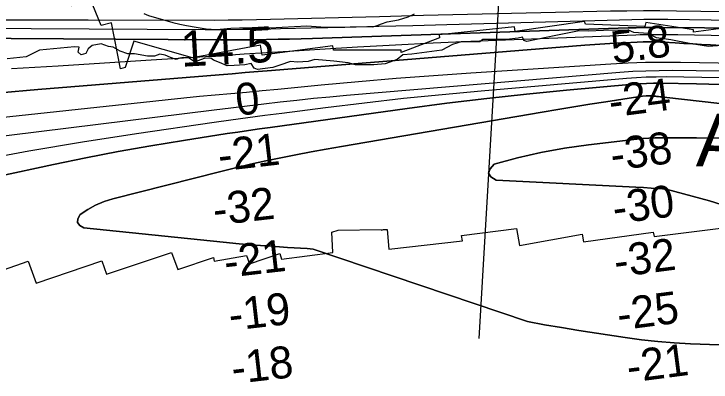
# Model space of a CAD drawing. Extents: x 3219052 to 3256913, y 800770 to 826146.
# Drawn here: x 3229358 to 3230665, y 817096 to 817787 of the extents above; entities that cross this region are included whole.
import ezdxf

# ---------------------------------------------------------------- set-up
doc = ezdxf.new("R2010")
doc.units = 0
for name, color, linetype in [('V-RIVR-EDGE', 7, 'Continuous'), ('V-RIVR-RANG', 7, 'Continuous'), ('V-RRAP-RVMT', 7, 'Continuous'), ('V-RRAP-RVMT-IDEN', 7, 'Continuous'), ('V-SITE-VEGE', 7, 'Continuous'), ('V-TOPO-DPTH', 7, 'Continuous'), ('V-TOPO-MINR', 7, 'Continuous'), ('V-TOPO-WATR', 7, 'Continuous')]:
    doc.layers.add(name, color=color, linetype=linetype)

msp = doc.modelspace()

# ---------------------------------------------------------------- linework, layer by layer
at = {"layer": 'V-RIVR-EDGE'}
for points in [[(3230693.3, 817727.8), (3230659.8, 817725.7), (3230624.2, 817731), (3230589.4, 817738.1), (3230562.5, 817741.6), (3230546.4, 817749.9), (3230519.9, 817752.1), (3230509.9, 817756.5), (3230463, 817755.8), (3230435.1, 817754.1), (3230417.3, 817755), (3230373.4, 817746), (3230319, 817735.2), (3230313.4, 817736.6), (3230310.8, 817743.1), (3230303, 817741.4), (3230281.2, 817738.8), (3230236.5, 817738.9), (3230231.2, 817734.6), (3230225.1, 817734.2), (3230196, 817734.2), (3230179.9, 817729.1), (3230159.9, 817718.7), (3230103.8, 817711.4), (3230086.9, 817709.7), (3230076, 817701.5), (3230053.8, 817692.9), (3230032.5, 817691.2), (3229998.1, 817691.3), (3229984.2, 817695.2), (3229957.3, 817698.3), (3229921.7, 817701), (3229909.5, 817697.6), (3229889, 817696.3), (3229876, 817697.2), (3229856.4, 817690.8), (3229842.9, 817686), (3229814.2, 817682.2), (3229808.2, 817685.2), (3229802.1, 817693.9), (3229790.4, 817691.3), (3229770.4, 817689.7), (3229757.3, 817689.3), (3229743, 817695.4), (3229731.7, 817699.8), (3229726.5, 817703.7), (3229714.3, 817702.8), (3229702.1, 817698.5), (3229695.6, 817697.7), (3229685.2, 817704.2), (3229675.6, 817704.7), (3229668.7, 817703.8), (3229661.7, 817701.2), (3229651.3, 817705.2), (3229641.3, 817709.5), (3229631.3, 817711.3), (3229621.3, 817707.4), (3229608.3, 817707.4), (3229583.5, 817711.9), (3229571.3, 817711.9), (3229556.6, 817717.1), (3229543.5, 817724.6), (3229534.8, 817725.9), (3229521.4, 817730.7), (3229504, 817727.7), (3229497, 817721.2), (3229492.7, 817712.5)], [(3229492.7, 817712.5), (3229483.5, 817709.9), (3229478.3, 817715.2), (3229480.1, 817724.3), (3229471.4, 817725.2), (3229405.7, 817718.8), (3229380.5, 817706.3), (3229344.8, 817702.4)]]:
    msp.add_lwpolyline(points, dxfattribs=at)
at = {"layer": 'V-RIVR-RANG'}
msp.add_line((3230269.4, 817868.1), (3230229, 817177.3), dxfattribs=at)
at = {"layer": 'V-RRAP-RVMT'}
for points in [[(3230083.5, 817714.2), (3230083.5, 817718.7), (3229956.5, 817718.7), (3229955.5, 817727.1), (3229822.9, 817709.5), (3229819.6, 817728.4), (3229692.5, 817704.4), (3229582.2, 817735.4), (3229566.3, 817686), (3229557.5, 817683.8), (3229540.8, 817769.9), (3229521.1, 817764.9), (3229499.8, 817817.6), (3229465.8, 817802.2), (3229392, 817823.7), (3229393, 817834.5), (3229255, 817843.4)], [(3230838.7, 817753.6), (3230834.2, 817753.3), (3230832.5, 817762.2), (3230690.4, 817741.2), (3230688.1, 817759.9), (3230631.6, 817752.8), (3230631.4, 817756.7), (3230542.5, 817770.8), (3230540.4, 817762.9), (3230428.9, 817767.3), (3230427.6, 817772.6), (3230297.1, 817753.7), (3230295.9, 817762.3), (3230155.1, 817747.8), (3230155.7, 817741.9), (3230083.5, 817714.2)], [(3229255.6, 817277.6), (3229384, 817322.5), (3229399.5, 817281.5), (3229522.4, 817323.2), (3229531.4, 817298), (3229653.3, 817339.2), (3229665, 817307.2), (3229731.8, 817329.4), (3229732.7, 817322.7), (3229793.7, 817333.3), (3229799.5, 817317.6), (3229856.2, 817336.9), (3229859.2, 817326.7), (3229955.8, 817339), (3229953.8, 817377), (3229965.3, 817381), (3230046.4, 817382), (3230046.8, 817381), (3230050.5, 817382.1), (3230057.3, 817382.1), (3230060.7, 817345.5), (3230198.3, 817361.1), (3230197, 817371), (3230300, 817384.1), (3230305.6, 817352.1), (3230423, 817373.4), (3230425.4, 817358.7), (3230556.3, 817377.4), (3230557.8, 817369), (3230812, 817401.2)]]:
    msp.add_lwpolyline(points, dxfattribs=at)
at = {"layer": 'V-SITE-VEGE'}
for p, q in [((3229601.3, 817787.3), (3229609.6, 817783.7)), ((3229609.6, 817783.7), (3229655.3, 817770.4)), ((3230078.7, 817775.4), (3230096.6, 817781.3)), ((3230096.6, 817781.3), (3230108.4, 817786.7)), ((3229655.3, 817770.4), (3229668.5, 817767.3)), ((3229668.5, 817767.3), (3229681.2, 817764.8)), ((3230038.7, 817764.8), (3230046.6, 817768.4)), ((3230046.6, 817768.4), (3230057.1, 817772.1)), ((3230057.1, 817772.1), (3230078.7, 817775.4)), ((3229681.2, 817764.8), (3229699.2, 817761.6)), ((3229699.2, 817761.6), (3229718.3, 817759)), ((3229718.3, 817759), (3229737.6, 817757.6)), ((3229737.6, 817757.6), (3229764.1, 817760.3)), ((3229764.1, 817760.3), (3229780.2, 817760.5)), ((3229780.2, 817760.5), (3229793.8, 817760.4)), ((3229793.8, 817760.4), (3229837.6, 817760.9)), ((3229837.6, 817760.9), (3229906.8, 817764.3)), ((3229906.8, 817764.3), (3229933.2, 817762.3)), ((3229933.2, 817762.3), (3229943.5, 817761.6)), ((3229943.5, 817761.6), (3229956.7, 817761.8)), ((3229956.7, 817761.8), (3230018.8, 817763.2)), ((3230018.8, 817763.2), (3230030.7, 817762.8)), ((3230030.7, 817762.8), (3230038.7, 817764.8))]:
    msp.add_line(p, q, dxfattribs=at)
at = {"layer": 'V-TOPO-DPTH'}
for points in [[(3229057.5, 817742.8), (3229744.6, 817738.1), (3229766.2, 817738), (3229787.8, 817738), (3229809.4, 817738.3), (3229831, 817738.6), (3229852.7, 817739.1), (3229874.3, 817739.6), (3229895.9, 817740.2), (3229917.5, 817740.9), (3230509, 817760.5), (3230524.1, 817760.9), (3230539.1, 817761.2), (3230554.2, 817761.2), (3230569.3, 817761.2), (3230652.5, 817760.4), (3230709.1, 817759.4)], [(3229331, 817638.8), (3229402.6, 817645), (3229742.5, 817672.6), (3229766.9, 817674.6), (3229791.4, 817676.6), (3229815.8, 817678.6), (3229840.2, 817680.5), (3230427.8, 817728), (3230446.5, 817729.4), (3230465.3, 817730.7), (3230484, 817731.8), (3230502.8, 817732.7), (3230537.2, 817734.3), (3230538.8, 817734.4), (3230540.3, 817734.4), (3230543.4, 817734.4), (3230552, 817734.4), (3230557.9, 817734.3), (3230563.8, 817734.1), (3230569.7, 817733.9), (3230575.6, 817733.6), (3230597, 817732.5), (3230613.6, 817731.5), (3230630.2, 817730.6), (3230646.8, 817729.6), (3230663.4, 817728.5), (3231005.5, 817707)], [(3231005.5, 817707), (3230663.4, 817728.5), (3230646.8, 817729.6), (3230630.2, 817730.6), (3230613.6, 817731.5), (3230597, 817732.5), (3230575.6, 817733.6), (3230569.7, 817733.9), (3230563.8, 817734.1), (3230557.9, 817734.3), (3230552, 817734.4), (3230543.4, 817734.4), (3230540.3, 817734.4), (3230538.8, 817734.4), (3230537.2, 817734.3), (3230502.8, 817732.7), (3230484, 817731.8), (3230465.3, 817730.7), (3230446.5, 817729.4), (3230427.8, 817728), (3229840.2, 817680.5), (3229815.8, 817678.6), (3229791.4, 817676.6), (3229766.9, 817674.6), (3229742.5, 817672.6), (3229402.6, 817645), (3229331, 817638.8)], [(3230725.5, 817678.7), (3230592, 817680.3), (3230567.3, 817680.2), (3230542.6, 817679.6), (3230518, 817678.4), (3230493.4, 817676.7), (3229981.1, 817633.5), (3229950.1, 817630.8), (3229919, 817627.8), (3229888, 817624.5), (3229857, 817621), (3229826, 817617.3), (3229795, 817613.6), (3229764, 817609.8), (3229733.1, 817606), (3229241.6, 817545.5)], [(3230725.5, 817678.7), (3230592, 817680.3), (3230567.3, 817680.2), (3230542.6, 817679.6), (3230518, 817678.4), (3230493.4, 817676.7), (3229981.1, 817633.5), (3229950.1, 817630.8), (3229919, 817627.8), (3229888, 817624.5), (3229857, 817621), (3229826, 817617.3), (3229795, 817613.6), (3229764, 817609.8), (3229733.1, 817606), (3229241.6, 817545.5)], [(3229327, 817481.4), (3229431.9, 817504.2), (3229492.5, 817516.8), (3229553.3, 817528.6), (3229614.2, 817539.3), (3229675.3, 817549.3), (3229757.6, 817562.1), (3229777.6, 817565.1), (3229797.6, 817568.1), (3229817.7, 817570.9), (3229837.7, 817573.8), (3230094.6, 817609.3), (3230169.2, 817619.1), (3230243.9, 817628.2), (3230318.7, 817636.1), (3230393.7, 817643.4), (3230518.3, 817654.6), (3230530.9, 817655.6), (3230543.6, 817656.3), (3230556.4, 817656.5), (3230569.1, 817656.6), (3230637, 817655.7), (3230683.6, 817654.5)], [(3229327, 817481.4), (3229431.9, 817504.2), (3229492.5, 817516.8), (3229553.3, 817528.6), (3229614.2, 817539.3), (3229675.3, 817549.3), (3229757.6, 817562.1), (3229777.6, 817565.1), (3229797.6, 817568.1), (3229817.7, 817570.9), (3229837.7, 817573.8), (3230094.6, 817609.3), (3230169.2, 817619.1), (3230243.9, 817628.2), (3230318.7, 817636.1), (3230393.7, 817643.4), (3230518.3, 817654.6), (3230530.9, 817655.6), (3230543.6, 817656.3), (3230556.4, 817656.5), (3230569.1, 817656.6), (3230637, 817655.7), (3230683.6, 817654.5)], [(3230819.4, 817603.1), (3230576.3, 817630.5), (3230572.9, 817630.9), (3230569.4, 817631.3), (3230566, 817631.7), (3230562.6, 817632), (3230561.2, 817632.2), (3230558.5, 817632.5), (3230555.7, 817632.7), (3230552.9, 817632.8), (3230550.2, 817632.9), (3230545.4, 817633), (3230543.9, 817632.9), (3230543.1, 817632.8), (3230536.1, 817632.2), (3230531.9, 817631.7), (3230527.6, 817631.2), (3230523.4, 817630.7), (3230519.2, 817630), (3230467.6, 817621.9), (3230437.6, 817617.1), (3230407.6, 817612.2), (3230377.6, 817607.2), (3230347.7, 817602.2), (3229971.7, 817538.1), (3229943.2, 817533.1), (3229914.7, 817528), (3229886.3, 817522.5), (3229858, 817516.9), (3229829.6, 817510.9), (3229801.4, 817504.7), (3229773.3, 817498), (3229745.2, 817491.1), (3229542.8, 817439.7), (3229526.5, 817434.5), (3229510.8, 817428), (3229496, 817419.6), (3229481.8, 817410), (3229477.7, 817402.1), (3229476.9, 817395.2), (3229481.2, 817389.7), (3229488.8, 817385.2), (3229749.9, 817358.4), (3229780, 817355.5), (3229810.1, 817352.9), (3229840.3, 817350.6), (3229870.4, 817348.5), (3229907.1, 817346.3), (3229918.9, 817345.1), (3230320.2, 817209.7), (3230352.2, 817203.5), (3230384.4, 817197.9), (3230416.6, 817192.7), (3230503.5, 817179.4), (3230534, 817175.3), (3230564.7, 817171.8), (3230595.4, 817169.4), (3230626.2, 817167.6), (3230679.7, 817165.4)], [(3230679.7, 817165.4), (3230626.2, 817167.6), (3230595.4, 817169.4), (3230564.7, 817171.8), (3230534, 817175.3), (3230503.5, 817179.4), (3230416.6, 817192.7), (3230384.4, 817197.9), (3230352.2, 817203.5), (3230320.2, 817209.7), (3229918.9, 817345.1), (3229907.1, 817346.3), (3229870.4, 817348.5), (3229840.3, 817350.6), (3229810.1, 817352.9), (3229780, 817355.5), (3229749.9, 817358.4), (3229488.8, 817385.2), (3229481.2, 817389.7), (3229476.9, 817395.2), (3229477.7, 817402.1), (3229481.8, 817410), (3229496, 817419.6), (3229510.8, 817428), (3229526.5, 817434.5), (3229542.8, 817439.7), (3229745.2, 817491.1), (3229773.3, 817498), (3229801.4, 817504.7), (3229829.6, 817510.9), (3229858, 817516.9), (3229886.3, 817522.5), (3229914.7, 817528), (3229943.2, 817533.1), (3229971.7, 817538.1), (3230347.7, 817602.2), (3230377.6, 817607.2), (3230407.6, 817612.2), (3230437.6, 817617.1), (3230467.6, 817621.9), (3230519.2, 817630), (3230523.4, 817630.7), (3230527.6, 817631.2), (3230531.9, 817631.7), (3230536.1, 817632.2), (3230543.1, 817632.8), (3230543.9, 817632.9), (3230545.4, 817633), (3230550.2, 817632.9), (3230552.9, 817632.8), (3230555.7, 817632.7), (3230558.5, 817632.5), (3230561.2, 817632.2), (3230562.6, 817632), (3230566, 817631.7), (3230569.4, 817631.3), (3230572.9, 817630.9), (3230576.3, 817630.5), (3230819.4, 817603.1)], [(3230682, 817553.7), (3230637.4, 817553.9), (3230570.7, 817554.1), (3230559.4, 817554), (3230548.1, 817553.5), (3230536.8, 817552.7), (3230525.5, 817551.6), (3230434.6, 817541), (3230390, 817534.6), (3230345.6, 817526.7), (3230301.8, 817516.5), (3230258.2, 817504.8), (3230250.2, 817496.1), (3230247.3, 817488.1), (3230252, 817481), (3230261.9, 817474.5), (3230523.5, 817461.6), (3230537.8, 817460.8), (3230552, 817460), (3230566.3, 817458.9), (3230580.6, 817457.8), (3230661.5, 817435.9), (3230790.5, 817395.1)], [(3230790.5, 817395.1), (3230661.5, 817435.9), (3230580.6, 817457.8), (3230566.3, 817458.9), (3230552, 817460), (3230537.8, 817460.8), (3230523.5, 817461.6), (3230261.9, 817474.5), (3230252, 817481), (3230247.3, 817488.1), (3230250.2, 817496.1), (3230258.2, 817504.8), (3230301.8, 817516.5), (3230345.6, 817526.7), (3230390, 817534.6), (3230434.6, 817541), (3230525.5, 817551.6), (3230536.8, 817552.7), (3230548.1, 817553.5), (3230559.4, 817554), (3230570.7, 817554.1), (3230637.4, 817553.9), (3230682, 817553.7)]]:
    msp.add_lwpolyline(points, dxfattribs=at)
at = {"layer": 'V-TOPO-MINR'}
for points in [[(3230826.8, 817788.7), (3230599.5, 817792.1), (3230568.6, 817792.4), (3230537.8, 817792.5), (3230506.9, 817792.2), (3230476, 817791.7), (3230372.9, 817789.4), (3230290.4, 817787.5), (3230207.9, 817785.6), (3230125.5, 817783.5), (3230043, 817781.4), (3229838.5, 817776), (3229812.1, 817775.4), (3229785.7, 817775), (3229759.3, 817774.8), (3229732.9, 817774.7), (3229496.5, 817775.2), (3229407.6, 817775.2), (3229318.6, 817774.9)], [(3230705.7, 817774.6), (3230583.7, 817776.1), (3230561.1, 817776.2), (3230538.5, 817776.2), (3230515.9, 817775.8), (3230493.2, 817775.3), (3230169.5, 817766.3), (3230105.7, 817764.5), (3230041.9, 817762.9), (3229978.1, 817761.3), (3229914.3, 817759.8), (3229857.3, 817758.5), (3229822, 817757.8), (3229786.7, 817757.3), (3229751.4, 817757.2), (3229716.1, 817757.2), (3229280.7, 817759.1)], [(3230709.1, 817759.4), (3230652.5, 817760.4), (3230569.3, 817761.2), (3230554.2, 817761.2), (3230539.1, 817761.2), (3230524.1, 817760.9), (3230509, 817760.5), (3229917.5, 817740.9), (3229895.9, 817740.2), (3229874.3, 817739.6), (3229852.7, 817739.1), (3229831, 817738.6), (3229809.4, 817738.3), (3229787.8, 817738), (3229766.2, 817738), (3229744.6, 817738.1), (3229057.5, 817742.8)], [(3230695.7, 817744.7), (3230664.5, 817746), (3230633.3, 817746.7), (3230602.1, 817747.2), (3230556.1, 817747.6), (3230547.9, 817747.6), (3230539.7, 817747.5), (3230531.6, 817747.3), (3230523.4, 817747), (3230214.5, 817734.7), (3230143.6, 817731.6), (3230072.7, 817728.2), (3230001.8, 817724.2), (3229931, 817720), (3229872.7, 817716.3), (3229831.1, 817713.7), (3229789.4, 817711), (3229747.7, 817708.4), (3229706, 817705.7), (3229614.9, 817699.9), (3229527.7, 817694.3), (3229440.4, 817688.9), (3229353.2, 817683.5)], [(3230855.3, 817691.1), (3230607.3, 817695.6), (3230574.6, 817695.8), (3230541.9, 817695.5), (3230509.3, 817694.3), (3230476.6, 817692.6), (3230214.5, 817675.6), (3230144.2, 817670.8), (3230074, 817665.4), (3230003.8, 817659.4), (3229933.7, 817653), (3229852.1, 817645.1), (3229822.8, 817642.3), (3229793.5, 817639.5), (3229764.2, 817636.8), (3229734.9, 817634.1), (3229705.6, 817631.5), (3229676.3, 817628.6), (3229647, 817625.7), (3229617.8, 817622.6), (3228993.8, 817555.3)], [(3230725.5, 817678.7), (3230592, 817680.3), (3230567.3, 817680.2), (3230542.6, 817679.6), (3230518, 817678.4), (3230493.4, 817676.7), (3229981.1, 817633.5), (3229950.1, 817630.8), (3229919, 817627.8), (3229888, 817624.5), (3229857, 817621), (3229826, 817617.3), (3229795, 817613.6), (3229764, 817609.8), (3229733.1, 817606), (3229241.6, 817545.5)], [(3230680.4, 817667.1), (3230580.5, 817668.4), (3230561.8, 817668.3), (3230543.1, 817667.9), (3230524.5, 817667), (3230505.8, 817665.6), (3230233.8, 817641.9), (3230160.7, 817635.1), (3230087.7, 817627.7), (3230014.7, 817619.4), (3229941.9, 817610.5), (3229859.9, 817600), (3229828.1, 817595.9), (3229796.3, 817591.6), (3229764.5, 817587.2), (3229732.8, 817582.7), (3229587.6, 817561.6), (3229486.4, 817546), (3229385.4, 817529), (3229284.7, 817510.1)], [(3230683.6, 817654.5), (3230637, 817655.7), (3230569.1, 817656.6), (3230556.4, 817656.5), (3230543.6, 817656.3), (3230530.9, 817655.6), (3230518.3, 817654.6), (3230393.7, 817643.4), (3230318.7, 817636.1), (3230243.9, 817628.2), (3230169.2, 817619.1), (3230094.6, 817609.3), (3229837.7, 817573.8), (3229817.7, 817570.9), (3229797.6, 817568.1), (3229777.6, 817565.1), (3229757.6, 817562.1), (3229675.3, 817549.3), (3229614.2, 817539.3), (3229553.3, 817528.6), (3229492.5, 817516.8), (3229431.9, 817504.2), (3229327, 817481.4)], [(3230819.4, 817603.1), (3230576.3, 817630.5), (3230572.9, 817630.9), (3230569.4, 817631.3), (3230566, 817631.7), (3230562.6, 817632), (3230561.2, 817632.2), (3230558.5, 817632.5), (3230555.7, 817632.7), (3230552.9, 817632.8), (3230550.2, 817632.9), (3230545.4, 817633), (3230543.9, 817632.9), (3230543.1, 817632.8), (3230536.1, 817632.2), (3230531.9, 817631.7), (3230527.6, 817631.2), (3230523.4, 817630.7), (3230519.2, 817630), (3230467.6, 817621.9), (3230437.6, 817617.1), (3230407.6, 817612.2), (3230377.6, 817607.2), (3230347.7, 817602.2), (3229971.7, 817538.1), (3229943.2, 817533.1), (3229914.7, 817528), (3229886.3, 817522.5), (3229858, 817516.9), (3229829.6, 817510.9), (3229801.4, 817504.7), (3229773.3, 817498), (3229745.2, 817491.1), (3229542.8, 817439.7), (3229526.5, 817434.5), (3229510.8, 817428), (3229496, 817419.6), (3229481.8, 817410), (3229477.7, 817402.1), (3229476.9, 817395.2), (3229481.2, 817389.7), (3229488.8, 817385.2), (3229749.9, 817358.4), (3229780, 817355.5), (3229810.1, 817352.9), (3229840.3, 817350.6), (3229870.4, 817348.5), (3229907.1, 817346.3), (3229918.9, 817345.1), (3230320.2, 817209.7), (3230352.2, 817203.5), (3230384.4, 817197.9), (3230416.6, 817192.7), (3230503.5, 817179.4), (3230534, 817175.3), (3230564.7, 817171.8), (3230595.4, 817169.4), (3230626.2, 817167.6), (3230679.7, 817165.4)], [(3230682, 817553.7), (3230637.4, 817553.9), (3230570.7, 817554.1), (3230559.4, 817554), (3230548.1, 817553.5), (3230536.8, 817552.7), (3230525.5, 817551.6), (3230434.6, 817541), (3230390, 817534.6), (3230345.6, 817526.7), (3230301.8, 817516.5), (3230258.2, 817504.8), (3230250.2, 817496.1), (3230247.3, 817488.1), (3230252, 817481), (3230261.9, 817474.5), (3230523.5, 817461.6), (3230537.8, 817460.8), (3230552, 817460), (3230566.3, 817458.9), (3230580.6, 817457.8), (3230661.5, 817435.9), (3230790.5, 817395.1)]]:
    msp.add_lwpolyline(points, dxfattribs=at)
at = {"layer": 'V-TOPO-WATR'}
msp.add_lwpolyline([(3231005.5, 817707), (3230663.4, 817728.5), (3230646.8, 817729.6), (3230630.2, 817730.6), (3230613.6, 817731.5), (3230597, 817732.5), (3230575.6, 817733.6), (3230569.7, 817733.9), (3230563.8, 817734.1), (3230557.9, 817734.3), (3230552, 817734.4), (3230543.4, 817734.4), (3230540.3, 817734.4), (3230538.8, 817734.4), (3230537.2, 817734.3), (3230502.8, 817732.7), (3230484, 817731.8), (3230465.3, 817730.7), (3230446.5, 817729.4), (3230427.8, 817728), (3229840.2, 817680.5), (3229815.8, 817678.6), (3229791.4, 817676.6), (3229766.9, 817674.6), (3229742.5, 817672.6), (3229402.6, 817645), (3229331, 817638.8)], dxfattribs=at)

# ---------------------------------------------------------------- texts
at = {"layer": 'V-RIVR-RANG'}
for s, height, rotation, p in [('14.5', 67, 3.1583, (3229671.8, 817687.5)), ('5.8', 60, 7.4237, (3230480.8, 817693.4)), ('-24', 60, 7.4237, (3230476.4, 817592.3)), ('0', 60, 6.5734, (3229776.5, 817595.4)), ('-21', 60, 6.5734, (3229743.3, 817491.1)), ('-38', 60, 7.4237, (3230479.6, 817492.3)), ('-32', 60, 6.5734, (3229733.8, 817389.5)), ('-30', 60, 7.4237, (3230483.6, 817392.3)), ('-21', 60, 6.5734, (3229754.8, 817291.4)), ('-32', 60, 7.4237, (3230486.3, 817292.2)), ('-19', 60, 6.5734, (3229763.4, 817191.9)), ('-25', 60, 7.4237, (3230492, 817192.5)), ('-21', 60, 7.4237, (3230510.1, 817094.4)), ('-18', 60, 6.5734, (3229768.5, 817092))]:
    msp.add_text(s, height=height, rotation=rotation, dxfattribs=at).set_placement(p)
at = {"layer": 'V-RRAP-RVMT-IDEN'}
msp.add_text('ARROW', height=100, rotation=358.7529, dxfattribs=at).set_placement((3230635.8, 817500.7))

doc.saveas('drawing.dxf')
